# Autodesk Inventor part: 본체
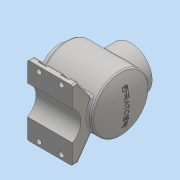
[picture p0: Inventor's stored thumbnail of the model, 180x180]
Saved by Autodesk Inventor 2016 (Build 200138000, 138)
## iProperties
Created: 2021-04
Part Number: 본체
Material: Generic
Document SubType Name: Modeling
Designer: User
Density: 1 g/cm^3
Appearance: Default
Author: User
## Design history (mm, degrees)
sketch "스케치2"
  geometry: L1 (-71.647, 0)-(96.782, 0); L2 (-33.773, 50)-(62.564, 50); L3 (-33.773, 50)-(-33.773, 38); L4 (-33.773, 38)-(-45.773, 38); L5 (-45.773, 38)-(-45.773, 0); A1 r 113 centre (-38.773, 0) between (74.227, 0) and (62.564, 50); 1 further point
  constraints: 10 end point, 3 horizontal, 3 point on line, 2 point on circle, 1 centre point, 1 perpendicular
  dimensions: "d0" = 100 diameter of L2 L1; "d1" = 76 diameter of L4 L1; "d5" = 12 distance of L3.end L4.end; "d6" = 226 diameter of A1; "d7" = 108 distance from line of A1.start L3
revolve "회전1" sketch "스케치2" stored, may be unused: angle "d2" = 90 deg
node "작업 평면1"
sketch "스케치3"
  geometry: L1 (-62, -77)-(-62, -67); L2 (62, -77)-(62, -67); L3 (62, -67)-(14.694, -33.876); L4 (-62, -67)-(-14.694, -33.876); L5 (-14.694, -33.876)-(14.694, -33.876); L6 (0, 0)-(50, 0.171); L7 (-62, -77)-(-25.981, -77); L8 (25.981, -77)-(62, -77); L9 (-25.981, -77)-(25.981, -77); L10 (0, 0)-(0, -77); A1 r 30 centre (0, -92) between (25.981, -77) and (-25.981, -77); 1 further point
  constraints: 20 end point, 4 horizontal, 2 parallel, 2 point on circle, 1 centre point, 1 collinear, 1 midpoint, 1 vertical
  dimensions: "d11" = 124 distance of L1.start L2.start; "d12" = 55 deg angle of L2 L3; "d13" = 10 distance of L2.start L2.end; "d15" = 77 distance of L6.start L10.end
extrude "돌출1" join sketch "스케치3" distance "d16" = 80; taper "d17" = 0 deg
node "작업 평면2"
sketch "스케치4"
  geometry: L1 (-8, -63.981)-(-8, 12.019) reference; L2 (-20, -63.981)-(-20, 12.019) reference; C1 r 38 at (42, -25.981); 1 further point
  constraints: 1 centre point
  dimensions: "d19" = 62 distance from line of C1.centre L2
extrude "돌출2" join sketch "스케치4" stored distance "d20" = 80; taper "d21" = 0 deg
sketch "스케치5"
  geometry: 1 further point
hole "구멍1" diameter "d24" = 54; stored, may be unused: countersink angle "d28" = 90 deg, drill point angle "d30" = 118 deg; dims "d22" = 10, "d23" = 10, "d25" = 6, "d26" = 4, "d27" = 2, "d29" = 40
sketch "스케치6"
  geometry: L1 (-33.773, -38)-(-33.773, 38) reference; L2 (-45.773, -38)-(-45.773, 38) reference; L3 (62.564, -50)-(62.564, 50) reference; L4 (56.163, -1.923)-(56.163, 0); L5 (56.163, 40)-(-23.773, 40); L6 (-23.773, 40)-(-23.773, 0); L7 (-23.773, 0)-(63.528, 0); L8 (-33.773, -50)-(-33.773, 50) reference; L9 (-33.773, 50)-(62.564, 50) reference; A1 r 113 centre (-38.773, 0) between (62.564, -50) and (62.564, 50) reference; A2 r 112.301 centre (-48.773, 0) between (63.528, 0) and (56.163, 40); 1 further point
  constraints: 8 end point, 2 point on circle, 1 centre point, 1 horizontal, 1 parallel, 1 point on line
  dimensions: "d31" = 10 distance of A1.centre A2.centre; "d32" = 10 distance between parallel lines of L6 L8; "d33" = 10 distance between parallel lines of L5 L9
revolve "회전2" sketch "스케치6" stored, may be unused: angle "d34" = 90 deg
hole "구멍2" diameter "d37" = 54; stored, may be unused: countersink angle "d41" = 90 deg, drill point angle "d43" = 0 deg; dims "d35" = 10, "d36" = 10, "d38" = 6, "d39" = 4, "d40" = 2, "d42" = 25
fillet "모깎기1" dims "d44" = 3
fillet "모깎기2" dims "d45" = 3
fillet "모깎기3" dims "d46" = 3
node "작업 평면3"
sketch "스케치7"
  geometry: L1 (80, -51.962)-(80, -84.981) reference; L2 (0, -51.962)-(80, -51.962) reference; L3 (0, -51.962)-(0, -84.981) reference; L4 (3, -87.981)-(77, -87.981) reference; L5 (3, 36.019)-(77, 36.019) reference; L6 (0, 33.019)-(0, 0) reference; L7 (0, 0)-(80, 0) reference; L8 (80, 33.019)-(80, 0) reference; L9 (25.773, -25.981)-(112.863, -25.981); L10 (53, 28.019)-(53, 48.493); L11 (53, 48.493)-(67, 48.493); L12 (67, 48.493)-(67, 28.019); L13 (13, 28.019)-(13, 49.686); L14 (13, 49.686)-(27, 49.686); L15 (27, 49.686)-(27, 28.019); L16 (13, -79.981)-(13, -96.968); L17 (13, -96.968)-(27, -96.968); L18 (27, -96.968)-(27, -79.981); L19 (53, -79.981)-(53, -96.968); L20 (53, -96.968)-(67, -96.968); L21 (67, -96.968)-(67, -79.981); A1 r 3 centre (77, -84.981) between (77, -87.981) and (80, -84.981) reference; A2 r 3 centre (3, -84.981) between (0, -84.981) and (3, -87.981) reference; A3 r 3 centre (77, 33.019) between (80, 33.019) and (77, 36.019) reference; A4 r 3 centre (3, 33.019) between (3, 36.019) and (0, 33.019) reference; A5 r 7 centre (60, -79.981) between (67, -79.981) and (53, -79.981); A6 r 7 centre (20, -79.981) between (27, -79.981) and (13, -79.981); A7 r 7 centre (20, 28.019) between (13, 28.019) and (27, 28.019); A8 r 7 centre (60, 28.019) between (53, 28.019) and (67, 28.019); 4 further points
  constraints: 26 end point, 8 point on circle, 4 centre point, 4 coincident, 4 parallel, 3 point on line, 2 symmetric about line, 1 horizontal
  dimensions: "d48" = 54 vertical distance of L9.start point (60, -79.981); "d49" = 20 distance from line of point (60, -79.981) L1; "d50" = 40 distance of point (20, -79.981) point (60, -79.981); "d51" = 14 diameter of A5; "d52" = 14 diameter of A6; "d53" = 14 diameter of A7; "d54" = 14 diameter of A8
extrude "돌출3" cut sketch "스케치7" distance "d55" = 20; taper "d56" = 0 deg
sketch "스케치8"
  geometry: L1 (53, -79.981)-(53, -86.701) reference; L2 (27, -86.701)-(53, -86.701) reference; L3 (27, -86.701)-(27, -79.981) reference; L4 (13, -79.981)-(13, -86.701) reference; L5 (3, -86.701)-(13, -86.701) reference; L6 (3, -56.204)-(3, -86.701) reference; L7 (77, -56.204)-(3, -56.204) reference; L8 (77, -86.701)-(77, -56.204) reference; L9 (67, -86.701)-(77, -86.701) reference; L10 (67, -86.701)-(67, -79.981) reference; L11 (27, 28.019)-(27, 34.74) reference; L12 (53, 34.74)-(27, 34.74) reference; L13 (53, 34.74)-(53, 28.019) reference; L14 (67, 28.019)-(67, 34.74) reference; L15 (77, 34.74)-(67, 34.74) reference; L16 (77, 4.242)-(77, 34.74) reference; L17 (3, 4.242)-(77, 4.242) reference; L18 (3, 34.74)-(3, 4.242) reference; L19 (13, 34.74)-(3, 34.74) reference; L20 (13, 34.74)-(13, 28.019) reference; C1 r 4.5 at (60, -79.981); C2 r 4.5 at (20, -79.981); C3 r 4.5 at (60, 28.019); C4 r 4.5 at (20, 28.019); A1 r 7 centre (20, -79.981) between (27, -79.981) and (13, -79.981) reference; A2 r 7 centre (60, -79.981) between (67, -79.981) and (53, -79.981) reference; A3 r 7 centre (60, 28.019) between (53, 28.019) and (67, 28.019) reference; A4 r 7 centre (20, 28.019) between (13, 28.019) and (27, 28.019) reference; 1 further point
  constraints: 4 centre point, 4 coincident
extrude "돌출4" cut sketch "스케치8" distance "d57" = 20; taper "d58" = 0 deg
fillet "모깎기4" dims "d59" = 3
fillet "모깎기5" dims "d60" = 3
chamfer "모따기1" distance "d61" = 1; stored, may be unused: second distance "d62" = 2, angle "d63" = 45 deg
node "작업 평면5"
  node "작업 평면4"
sketch "스케치9"
  geometry: L1 (29.513, 27)-(65, 27) reference; C1 r 48.282 at (0, 0) reference; 2 further points
  constraints: 1 coincident, 1 other
feature "엠보싱1" sketch "스케치9" dims "d0" = 100, "d1" = 76, "d5" = 12, "d6" = 226, "d7" = 108, "d15" = 77, "d65" = 0.5, "d66" = 0
sketch "스케치11"
  geometry: C1 r 38 at (0, 0) reference; C2 r 28 at (0, 0) reference; A1 r 32.5 centre (0, 0) between (-32.5, 0) and (0, 32.5); 3 further points
  constraints: 4 point on circle, 1 centre point, 1 coincident
hole "구멍3" sketch "스케치11" at (0, 32.5), (32.5, 0), (0, -32.5), (-32.5, 0) diameter "d67" = 3.242; stored, may be unused: countersink angle "d71" = 90 deg, drill point angle "d73" = 118 deg; dims "d68" = 8, "d69" = 4, "d70" = 2, "d72" = 10
sketch "스케치12"
  geometry: C1 r 27 at (0, 0) reference; C2 r 38 at (0, 0) reference; A1 r 32.5 centre (0, 0) between (-32.5, 0) and (0, 32.5); 3 further points
  constraints: 4 point on circle, 1 centre point, 1 coincident
hole "구멍4" sketch "스케치12" at (0, 32.5), (32.5, 0), (0, -32.5), (-32.5, 0) diameter "d74" = 3.242; stored, may be unused: countersink angle "d78" = 90 deg, drill point angle "d80" = 118 deg; dims "d75" = 8, "d76" = 4, "d77" = 2, "d79" = 10
node "솔리드1"
node "투영된 루프3"
node "투영된 루프4"
node "투영된 루프5"
node "투영된 루프6"
node "투영된 루프7"
node "투영된 루프8"
node "투영된 루프9"
node "투영된 루프10"
node "투영된 루프11"
other parameters: "d14" = 15, "d18" = -142, "d47" = -6, "d64" = 0.5
